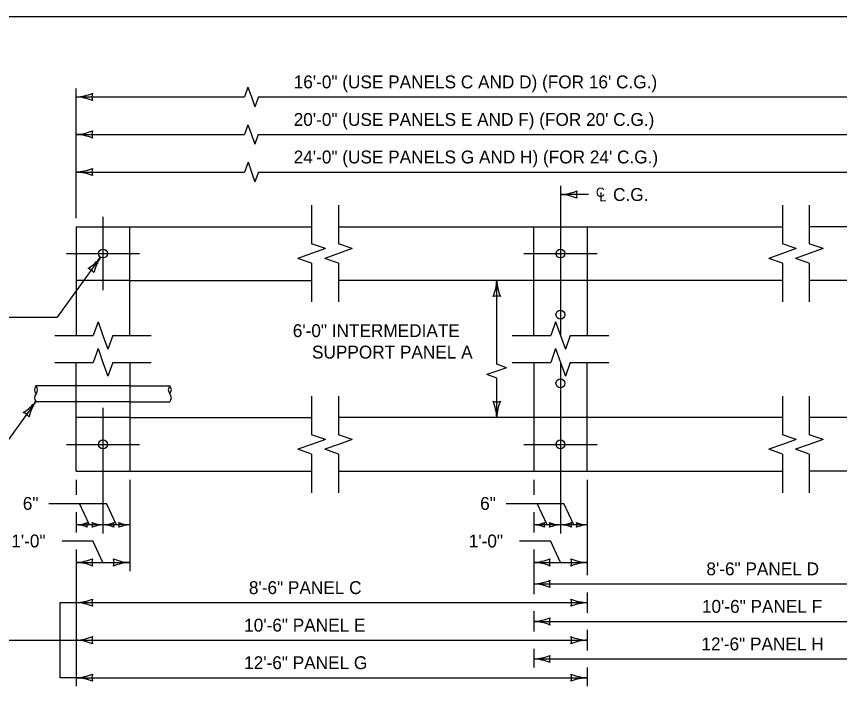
# Model space of a CAD drawing. Extents: x 49991.4 to 50021, y 49987.6 to 50011.4.
# Drawn here: x 50001.425 to 50005.265, y 49995.82 to 49998.999 of the extents above; entities that cross this region are included whole.
import ezdxf

# ---------------------------------------------------------------- set-up
doc = ezdxf.new("R2010")
doc.units = 0
for name, color, linetype in [('Level 1', 7, 'Continuous'), ('Level 10', 7, 'Continuous'), ('Level 2', 7, 'Continuous'), ('Level 3', 7, 'Continuous'), ('Level 4', 7, 'Continuous'), ('Level 5', 7, 'Continuous'), ('Level 6', 7, 'Continuous')]:
    doc.layers.add(name, color=color, linetype=linetype)

msp = doc.modelspace()

# ---------------------------------------------------------------- linework, layer by layer
at = {"layer": 'Level 1'}
for p, q in [((50001.7038, 49998.0191), (50002.8021, 49998.0191)), ((50001.7038, 49998.0191), (50001.7038, 49997.5116)), ((50001.9538, 49997.5116), (50001.9538, 49998.0191)), ((50002.9271, 49998.0191), (50004.9986, 49998.0191)), ((50003.8378, 49997.5116), (50003.8378, 49998.0191)), ((50006.2218, 49998.0191), (50005.1236, 49998.0191)), ((50001.9538, 49997.7691), (50002.8021, 49997.7691)), ((50004.9986, 49997.7691), (50002.9271, 49997.7691)), ((50004.0878, 49997.7691), (50004.0878, 49997.5116)), ((50005.9718, 49997.7691), (50005.1236, 49997.7691)), ((50001.7038, 49996.8791), (50001.7038, 49997.3866)), ((50001.9538, 49997.3866), (50001.9538, 49996.8791)), ((50003.8378, 49997.3866), (50003.8378, 49996.8791)), ((50004.0878, 49997.1291), (50004.0878, 49997.3866)), ((50001.7038, 49997.2775), (50001.5163, 49997.2775)), ((50001.9538, 49997.2775), (50002.1406, 49997.2775)), ((50001.7038, 49997.2025), (50001.5165, 49997.2025)), ((50001.9538, 49997.2025), (50002.1404, 49997.2025)), ((50001.9538, 49997.1291), (50002.8021, 49997.1291)), ((50004.9986, 49997.1291), (50002.9271, 49997.1291)), ((50005.9718, 49997.1291), (50005.1236, 49997.1291)), ((50001.7038, 49996.8791), (50002.8021, 49996.8791)), ((50002.9271, 49996.8791), (50004.9986, 49996.8791)), ((50006.2218, 49996.8791), (50005.1236, 49996.8791))]:
    msp.add_line(p, q, dxfattribs=at)
msp.add_lwpolyline([(49999.3835, 49998.9992), (50016.7501, 49998.9992), (50016.7501, 49987.7988), (49999.3835, 49987.7988)], close=True, dxfattribs=at)
for centre in [(50001.8287, 49997.8941), (50003.9627, 49997.8941), (50003.9627, 49997.6091), (50003.9627, 49997.2891), (50001.8287, 49997.0041), (50003.9627, 49997.0041)]:
    msp.add_circle(centre, 0.0208, dxfattribs=at)
for centre, radius, start, end in [((50001.5372, 49997.2587), 0.0281, 138.1897, 222.2069), ((50001.4962, 49997.2586), 0.0276, 317.2001, 43.1965), ((50002.1616, 49997.2587), 0.0281, 138.1897, 221.8103), ((50002.1197, 49997.2587), 0.0281, 318.1897, 41.8103), ((50001.5375, 49997.2212), 0.0281, 138.5839, 221.8103), ((50002.1198, 49997.2214), 0.0279, 317.4205, 41.7887)]:
    msp.add_arc(centre, radius, start, end, dxfattribs=at)
at = {"layer": 'Level 3'}
for p, q in [((50002.505, 49998.6698), (50002.4888, 49998.6241)), ((50002.505, 49998.6698), (50002.5212, 49998.6241)), ((50001.7038, 49998.0591), (50001.7038, 49998.6641)), ((50001.7038, 49998.6241), (50002.4888, 49998.6241)), ((50002.5212, 49998.6241), (50002.5374, 49998.5784)), ((50002.5536, 49998.6241), (50002.5374, 49998.5784)), ((50002.5536, 49998.6241), (50005.4042, 49998.6241)), ((50002.5048, 49998.4948), (50002.4886, 49998.4491)), ((50002.5048, 49998.4948), (50002.521, 49998.4491)), ((50001.7038, 49998.4491), (50002.4886, 49998.4491)), ((50002.521, 49998.4491), (50002.5372, 49998.4034)), ((50002.5534, 49998.4491), (50002.5372, 49998.4034)), ((50002.5534, 49998.4491), (50005.4042, 49998.4491)), ((50002.5053, 49998.3198), (50002.4891, 49998.2741)), ((50002.5053, 49998.3198), (50002.5215, 49998.2741)), ((50001.7038, 49998.2741), (50002.4891, 49998.2741)), ((50002.5215, 49998.2741), (50002.5377, 49998.2284)), ((50002.5539, 49998.2741), (50002.5377, 49998.2284)), ((50002.5539, 49998.2741), (50005.4041, 49998.2741)), ((50004.0938, 49998.1691), (50003.9628, 49998.1691)), ((50001.817, 49997.8768), (50001.6157, 49997.5969)), ((50003.6656, 49997.3782), (50003.6656, 49997.7691)), ((50000.7897, 49997.5969), (50001.6157, 49997.5969)), ((50003.7113, 49997.362), (50003.6656, 49997.3782)), ((50003.6656, 49997.3458), (50003.6199, 49997.3296)), ((50003.6656, 49997.3134), (50003.6199, 49997.3296)), ((50003.7113, 49997.362), (50003.6656, 49997.3458)), ((50003.6656, 49997.1291), (50003.6656, 49997.3134)), ((50001.5149, 49997.2046), (50001.3035, 49996.9108)), ((50001.7038, 49996.8391), (50001.7038, 49996.7691)), ((50001.9538, 49996.8391), (50001.9538, 49996.4141)), ((50003.8378, 49996.8391), (50003.8378, 49996.7691)), ((50004.0878, 49996.8391), (50004.0878, 49996.3941)), ((50001.5755, 49996.7291), (50001.8445, 49996.7291)), ((50001.7663, 49996.6291), (50001.7195, 49996.7291)), ((50001.8913, 49996.6291), (50001.8445, 49996.7291)), ((50003.7095, 49996.7291), (50003.9785, 49996.7291)), ((50003.9003, 49996.6291), (50003.8535, 49996.7291)), ((50004.0253, 49996.6291), (50003.9785, 49996.7291)), ((50001.7038, 49996.6891), (50001.7038, 49996.5941)), ((50003.8378, 49996.6891), (50003.8378, 49996.5941)), ((50001.8288, 49996.6291), (50001.7038, 49996.6291)), ((50001.9538, 49996.6291), (50001.8288, 49996.6291)), ((50003.9628, 49996.6291), (50003.8378, 49996.6291)), ((50004.0878, 49996.6291), (50003.9628, 49996.6291)), ((50001.638, 49996.5541), (50001.782, 49996.5541)), ((50001.8288, 49996.4541), (50001.782, 49996.5541)), ((50003.772, 49996.5541), (50003.916, 49996.5541)), ((50003.9628, 49996.4541), (50003.916, 49996.5541)), ((50001.7038, 49996.5141), (50001.7038, 49995.8766)), ((50003.8378, 49996.5141), (50003.8378, 49996.3066)), ((50001.7038, 49996.4541), (50001.9538, 49996.4541)), ((50003.8378, 49996.4541), (50004.0878, 49996.4541)), ((50003.8378, 49996.3541), (50006.2218, 49996.3541)), ((50004.0878, 49996.3141), (50004.0878, 49996.2191)), ((50001.6288, 49995.9166), (50001.6288, 49996.2666)), ((50001.6288, 49996.2666), (50001.7038, 49996.2666)), ((50001.7038, 49996.2666), (50004.0878, 49996.2666)), ((50003.8378, 49996.2266), (50003.8378, 49996.1316)), ((50003.8378, 49996.1791), (50006.2218, 49996.1791)), ((50004.0878, 49996.1391), (50004.0878, 49996.0441)), ((50000.8395, 49996.0916), (50001.7038, 49996.0916)), ((50001.7038, 49996.0916), (50004.0878, 49996.0916)), ((50003.8378, 49996.0516), (50003.8378, 49995.9641)), ((50003.8378, 49996.0041), (50006.2218, 49996.0041)), ((50004.0878, 49995.9641), (50004.0878, 49995.8766)), ((50001.7038, 49995.9166), (50001.6288, 49995.9166)), ((50001.7038, 49995.9166), (50004.0878, 49995.9166))]:
    msp.add_line(p, q, dxfattribs=at)
for centre, radius, start, end in [((50001.6923, 49998.8568), 0.233, 272.8273, 292.0772), ((50001.832, 49998.6241), 0.0548, 162.1388, 197.8612), ((50001.6946, 49998.402), 0.2223, 67.456, 87.6395), ((50001.6923, 49998.6818), 0.233, 272.8273, 292.0772), ((50001.6946, 49998.227), 0.2223, 67.456, 87.6395), ((50001.832, 49998.4491), 0.0548, 162.1388, 197.8612), ((50001.6923, 49998.5068), 0.233, 272.8273, 292.0772), ((50001.832, 49998.2741), 0.0548, 162.1388, 197.8612), ((50001.6946, 49998.052), 0.2223, 67.456, 87.6395), ((50003.9513, 49998.4018), 0.233, 272.8273, 292.0772), ((50004.091, 49998.1691), 0.0548, 162.1388, 197.8612), ((50003.9536, 49997.947), 0.2223, 67.456, 87.6395), ((50001.6421, 49998.014), 0.2223, 301.7291, 321.9126), ((50002.0127, 49997.7503), 0.233, 147.1004, 166.3502), ((50001.7422, 49997.7727), 0.0548, 36.4119, 72.1343), ((50003.4435, 49997.7783), 0.2223, 337.456, 357.6395), ((50003.8983, 49997.7806), 0.233, 182.8273, 202.0772), ((50003.6656, 49997.6409), 0.0548, 72.1388, 107.8612), ((50001.3399, 49997.3417), 0.2223, 301.7291, 321.9126), ((50001.7105, 49997.078), 0.233, 147.1004, 166.3502), ((50003.6656, 49997.2573), 0.0548, 252.1388, 287.8612), ((50003.4329, 49997.1176), 0.233, 2.8273, 22.0772), ((50003.8877, 49997.1199), 0.2223, 157.456, 177.6395), ((50001.44, 49997.1005), 0.0548, 36.4119, 72.1343), ((50001.6961, 49996.7842), 0.1553, 272.8273, 292.0772), ((50001.7893, 49996.6291), 0.0365, 162.1388, 197.8612), ((50001.8349, 49996.7772), 0.1482, 247.456, 267.6395), ((50001.7433, 49996.6291), 0.0365, 342.1388, 17.8612), ((50001.8211, 49996.7842), 0.1553, 272.8273, 292.0772), ((50001.9143, 49996.6291), 0.0365, 162.1388, 197.8612), ((50001.9599, 49996.7772), 0.1482, 247.456, 267.6395), ((50001.8683, 49996.6291), 0.0365, 342.1388, 17.8612), ((50003.8301, 49996.7842), 0.1553, 272.8273, 292.0772), ((50003.9233, 49996.6291), 0.0365, 162.1388, 197.8612), ((50003.9689, 49996.7772), 0.1482, 247.456, 267.6395), ((50003.8773, 49996.6291), 0.0365, 342.1388, 17.8612), ((50003.9551, 49996.7842), 0.1553, 272.8273, 292.0772), ((50004.0483, 49996.6291), 0.0365, 162.1388, 197.8612), ((50004.0939, 49996.7772), 0.1482, 247.456, 267.6395), ((50004.0023, 49996.6291), 0.0365, 342.1388, 17.8612), ((50001.6977, 49996.481), 0.1482, 67.456, 87.6395), ((50001.8365, 49996.474), 0.1553, 92.8273, 112.0772), ((50001.8227, 49996.481), 0.1482, 67.456, 87.6395), ((50001.9615, 49996.474), 0.1553, 92.8273, 112.0772), ((50003.8317, 49996.481), 0.1482, 67.456, 87.6395), ((50003.9705, 49996.474), 0.1553, 92.8273, 112.0772), ((50003.9567, 49996.481), 0.1482, 67.456, 87.6395), ((50004.0955, 49996.474), 0.1553, 92.8273, 112.0772), ((50001.6923, 49996.6868), 0.233, 272.8273, 292.0772), ((50001.6946, 49996.232), 0.2223, 67.456, 87.6395), ((50001.832, 49996.4541), 0.0548, 162.1388, 197.8612), ((50001.963, 49996.6762), 0.2223, 247.456, 267.6395), ((50001.8256, 49996.4541), 0.0548, 342.1388, 17.8612), ((50001.9653, 49996.2214), 0.233, 92.8273, 112.0772), ((50003.8263, 49996.6868), 0.233, 272.8273, 292.0772), ((50003.8286, 49996.232), 0.2223, 67.456, 87.6395), ((50003.966, 49996.4541), 0.0548, 162.1388, 197.8612), ((50004.097, 49996.6762), 0.2223, 247.456, 267.6395), ((50003.9596, 49996.4541), 0.0548, 342.1388, 17.8612), ((50004.0993, 49996.2214), 0.233, 92.8273, 112.0772), ((50003.8263, 49996.5868), 0.233, 272.8273, 292.0772), ((50003.966, 49996.3541), 0.0548, 162.1388, 197.8612), ((50003.8286, 49996.132), 0.2223, 67.456, 87.6395), ((50001.6923, 49996.4993), 0.233, 272.8273, 292.0772), ((50001.6946, 49996.0445), 0.2223, 67.456, 87.6395), ((50001.832, 49996.2666), 0.0548, 162.1388, 197.8612), ((50004.097, 49996.4887), 0.2223, 247.456, 267.6395), ((50003.9596, 49996.2666), 0.0548, 342.1388, 17.8612), ((50004.0993, 49996.0339), 0.233, 92.8273, 112.0772), ((50003.8263, 49996.4118), 0.233, 272.8273, 292.0772), ((50003.8286, 49995.957), 0.2223, 67.456, 87.6395), ((50003.966, 49996.1791), 0.0548, 162.1388, 197.8612), ((50001.6923, 49996.3243), 0.233, 272.8273, 292.0772), ((50001.832, 49996.0916), 0.0548, 162.1388, 197.8612), ((50004.097, 49996.3137), 0.2223, 247.456, 267.6395), ((50003.9596, 49996.0916), 0.0548, 342.1388, 17.8612), ((50001.6946, 49995.8695), 0.2223, 67.456, 87.6395), ((50004.0993, 49995.8589), 0.233, 92.8273, 112.0772), ((50003.8263, 49996.2368), 0.233, 272.8273, 292.0772), ((50003.966, 49996.0041), 0.0548, 162.1388, 197.8612), ((50003.8286, 49995.782), 0.2223, 67.456, 87.6395), ((50001.6923, 49996.1493), 0.233, 272.8273, 292.0772), ((50001.6946, 49995.6945), 0.2223, 67.456, 87.6395), ((50001.832, 49995.9166), 0.0548, 162.1388, 197.8612), ((50004.097, 49996.1387), 0.2223, 247.456, 267.6395), ((50003.9596, 49995.9166), 0.0548, 342.1388, 17.8612), ((50004.0993, 49995.6839), 0.233, 92.8273, 112.0772)]:
    msp.add_arc(centre, radius, start, end, dxfattribs=at)
at = {"layer": 'Level 4'}
for p, q in [((50004.0878, 49998.0191), (50004.0878, 49997.7691)), ((50001.9538, 49997.7691), (50001.7038, 49997.7691)), ((50001.9538, 49997.2775), (50001.7038, 49997.2775)), ((50001.9538, 49997.2025), (50001.7038, 49997.2025)), ((50001.9538, 49997.1291), (50001.7038, 49997.1291)), ((50004.0878, 49996.8791), (50004.0878, 49997.1291))]:
    msp.add_line(p, q, dxfattribs=at)
at = {"layer": 'Level 5'}
for p, q in [((50003.9628, 49998.2091), (50003.9628, 49997.5116)), ((50001.8288, 49998.0649), (50001.8288, 49997.7232)), ((50001.6579, 49997.8941), (50001.9996, 49997.8941)), ((50003.7919, 49997.8941), (50004.1336, 49997.8941)), ((50003.9628, 49997.3866), (50003.9628, 49996.5891)), ((50001.8288, 49997.1749), (50001.8288, 49996.5891)), ((50001.6579, 49997.0041), (50001.9996, 49997.0041)), ((50003.7919, 49997.0041), (50004.1336, 49997.0041))]:
    msp.add_line(p, q, dxfattribs=at)
at = {"layer": 'Level 6'}
for p, q in [((50002.8021, 49998.1191), (50002.8021, 49997.9395)), ((50002.9271, 49998.1191), (50002.9271, 49997.9395)), ((50004.9986, 49998.1191), (50004.9986, 49997.9395)), ((50005.1236, 49998.1191), (50005.1236, 49997.9395)), ((50002.8661, 49997.9168), (50002.8021, 49997.9395)), ((50002.8661, 49997.9168), (50002.8021, 49997.8941)), ((50002.9911, 49997.9168), (50002.9271, 49997.9395)), ((50002.9911, 49997.9168), (50002.9271, 49997.8941)), ((50005.0626, 49997.9168), (50004.9986, 49997.9395)), ((50005.0626, 49997.9168), (50004.9986, 49997.8941)), ((50005.1876, 49997.9168), (50005.1236, 49997.9395)), ((50005.1876, 49997.9168), (50005.1236, 49997.8941)), ((50002.8021, 49997.8941), (50002.7381, 49997.8714)), ((50002.8021, 49997.8487), (50002.7381, 49997.8714)), ((50002.9271, 49997.8941), (50002.8631, 49997.8714)), ((50002.9271, 49997.8487), (50002.8631, 49997.8714)), ((50004.9986, 49997.8941), (50004.9346, 49997.8714)), ((50004.9986, 49997.8487), (50004.9346, 49997.8714)), ((50005.1236, 49997.8941), (50005.0596, 49997.8714)), ((50005.1236, 49997.8487), (50005.0596, 49997.8714)), ((50002.8021, 49997.8487), (50002.8021, 49997.6691)), ((50002.9271, 49997.8487), (50002.9271, 49997.6691)), ((50004.9986, 49997.8487), (50004.9986, 49997.6691)), ((50005.1236, 49997.8487), (50005.1236, 49997.6691)), ((50001.8061, 49997.5756), (50001.7834, 49997.5116)), ((50001.8061, 49997.5756), (50001.8288, 49997.5116)), ((50003.9401, 49997.5756), (50003.9174, 49997.5116)), ((50003.9401, 49997.5756), (50003.9628, 49997.5116)), ((50001.6038, 49997.5116), (50001.7834, 49997.5116)), ((50001.8288, 49997.5116), (50001.8515, 49997.4476)), ((50001.8742, 49997.5116), (50001.8515, 49997.4476)), ((50001.8742, 49997.5116), (50002.0538, 49997.5116)), ((50003.7378, 49997.5116), (50003.9174, 49997.5116)), ((50003.9628, 49997.5116), (50003.9855, 49997.4476)), ((50004.0082, 49997.5116), (50003.9855, 49997.4476)), ((50004.0082, 49997.5116), (50004.1878, 49997.5116)), ((50001.8061, 49997.4506), (50001.7834, 49997.3866)), ((50001.8061, 49997.4506), (50001.8288, 49997.3866)), ((50003.9401, 49997.4506), (50003.9174, 49997.3866)), ((50003.9401, 49997.4506), (50003.9628, 49997.3866)), ((50001.6038, 49997.3866), (50001.7834, 49997.3866)), ((50001.8288, 49997.3866), (50001.8515, 49997.3226)), ((50001.8742, 49997.3866), (50001.8515, 49997.3226)), ((50001.8742, 49997.3866), (50002.0538, 49997.3866)), ((50003.7378, 49997.3866), (50003.9174, 49997.3866)), ((50003.9628, 49997.3866), (50003.9855, 49997.3226)), ((50004.0082, 49997.3866), (50003.9855, 49997.3226)), ((50004.0082, 49997.3866), (50004.1878, 49997.3866)), ((50002.8021, 49997.2291), (50002.8021, 49997.0495)), ((50002.9271, 49997.2291), (50002.9271, 49997.0495)), ((50004.9986, 49997.2291), (50004.9986, 49997.0495)), ((50005.1236, 49997.2291), (50005.1236, 49997.0495)), ((50002.8661, 49997.0268), (50002.8021, 49997.0495)), ((50002.8661, 49997.0268), (50002.8021, 49997.0041)), ((50002.9911, 49997.0268), (50002.9271, 49997.0495)), ((50002.9911, 49997.0268), (50002.9271, 49997.0041)), ((50005.0626, 49997.0268), (50004.9986, 49997.0495)), ((50005.0626, 49997.0268), (50004.9986, 49997.0041)), ((50005.1876, 49997.0268), (50005.1236, 49997.0495)), ((50005.1876, 49997.0268), (50005.1236, 49997.0041)), ((50002.8021, 49997.0041), (50002.7381, 49996.9814)), ((50002.8021, 49996.9587), (50002.7381, 49996.9814)), ((50002.9271, 49997.0041), (50002.8631, 49996.9814)), ((50002.9271, 49996.9587), (50002.8631, 49996.9814)), ((50004.9986, 49997.0041), (50004.9346, 49996.9814)), ((50004.9986, 49996.9587), (50004.9346, 49996.9814)), ((50005.1236, 49997.0041), (50005.0596, 49996.9814)), ((50005.1236, 49996.9587), (50005.0596, 49996.9814)), ((50002.8021, 49996.9587), (50002.8021, 49996.7791)), ((50002.9271, 49996.9587), (50002.9271, 49996.7791)), ((50004.9986, 49996.9587), (50004.9986, 49996.7791)), ((50005.1236, 49996.9587), (50005.1236, 49996.7791))]:
    msp.add_line(p, q, dxfattribs=at)

# ---------------------------------------------------------------- texts
at = {"layer": 'Level 10'}
for s, p in [('C', (50004.1282, 49998.158)), ('L', (50004.1446, 49998.1368))]:
    msp.add_text(s, height=0.0432, dxfattribs=at).set_placement(p)
at = {"layer": 'Level 2'}
for s, p in [('16\'-0" (USE PANELS C AND D) (FOR 16\' C.G.)', (50002.7184, 49998.6641)), ('20\'-0" (USE PANELS E AND F) (FOR 20\' C.G.)', (50002.7185, 49998.4891)), ('24\'-0" (USE PANELS G AND H) (FOR 24\' C.G.)', (50002.7184, 49998.3141)), ('C.G.', (50004.2081, 49998.1391)), ('6\'-0" INTERMEDIATE', (50002.7141, 49997.5046)), ('SUPPORT PANEL A', (50002.8039, 49997.4046)), ('6"', (50001.4548, 49996.6991)), ('6"', (50003.5882, 49996.6991)), ('1\'-0"', (50001.4011, 49996.5241)), ('1\'-0"', (50003.5351, 49996.5241)), (' 8\'-6" PANEL D', (50004.6212, 49996.3941)), (' 8\'-6" PANEL C', (50002.4872, 49996.3066)), ('10\'-6" PANEL F', (50004.6226, 49996.2191)), ('10\'-6" PANEL E', (50002.4874, 49996.1316)), ('12\'-6" PANEL H', (50004.6202, 49996.0441)), ('12\'-6" PANEL G', (50002.4872, 49995.9566))]:
    msp.add_text(s, height=0.06, dxfattribs=at).set_placement(p)

doc.saveas('drawing.dxf')
